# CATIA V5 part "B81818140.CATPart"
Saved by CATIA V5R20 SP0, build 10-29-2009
Part number: B81818140
Revision: 4
Definition: design
Nomenclature: B81818140
Source: made
Description: NOT SPECIFIED
Bounding box of the stored display mesh (mm): x -10.833 to 10.833, y -11 to 11, z 0 to 140
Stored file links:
  C:\Users\Raffaele\Desktop\3D X SITO CF\BOLEX\6-PILLAR REF 818\B81818140.CATPart
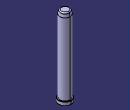
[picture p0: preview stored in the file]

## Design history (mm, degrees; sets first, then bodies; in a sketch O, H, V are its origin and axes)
Body1 "MANIFOLD_SOLID_BREP #370" (main body)
  Solid1: solid without history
